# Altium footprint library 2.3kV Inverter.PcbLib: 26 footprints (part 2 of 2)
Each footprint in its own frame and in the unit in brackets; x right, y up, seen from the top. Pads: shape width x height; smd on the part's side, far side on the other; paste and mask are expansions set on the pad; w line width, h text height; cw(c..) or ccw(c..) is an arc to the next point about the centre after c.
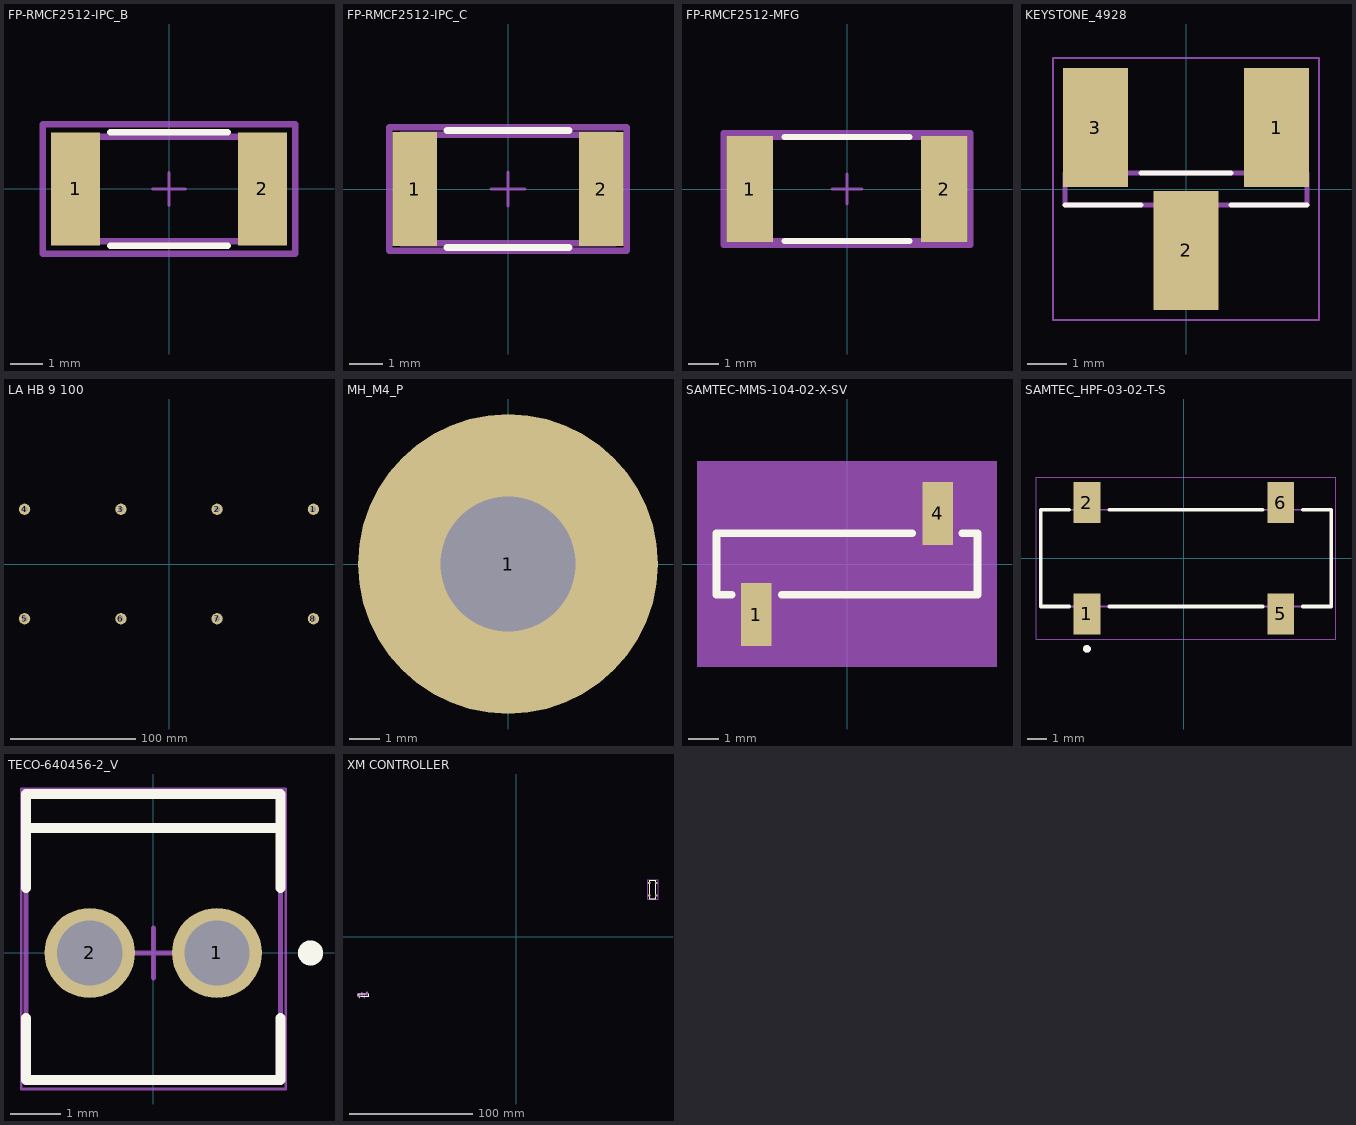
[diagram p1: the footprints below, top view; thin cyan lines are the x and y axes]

## FP-RMCF2512-IPC_B [mm]
pads (2):
  rect 1.504x3.455 smd paste+0 mask+0: 1(-2.851,0) 2(2.851,0)
Top Overlay:
  lines w0.2: -1.799,-1.727 1.799,-1.727 ; -1.799,1.727 1.799,1.727
Top Courtyard:
  lines w0.2: -3.853,-1.977 -3.853,1.977 3.853,1.977 3.853,-1.977 -3.853,-1.977
Top 3D Body:
  lines w0.2: -3.15,-1.6 -3.15,1.6 3.15,1.6 3.15,-1.6 -3.15,-1.6
Top Component Center:
  lines w0.1: -0.5,0 0.5,0 ; 0,-0.5 0,0.5
Top Assembly:
  lines w0.2: -3.853,-1.977 -3.853,1.977 3.853,1.977 3.853,-1.977 -3.853,-1.977
  text ".Designator" at 0,0.188 h1
3D body "Res_Stackpole_RMCF2512FT10M0_eec.STEP": height 0.25, standoff 0, extent -3.853,-1.977 3.853,1.977

## FP-RMCF2512-IPC_C [mm]
pads (2):
  rect 1.304x3.355 smd paste+0 mask+0: 1(-2.751,0) 2(2.751,0)
Top Overlay:
  lines w0.2: -1.799,-1.725 1.799,-1.725 ; -1.799,1.725 1.799,1.725
Top Courtyard:
  lines w0.2: -3.503,-1.825 -3.503,1.825 3.503,1.825 3.503,-1.825 -3.503,-1.825
Top 3D Body:
  lines w0.2: -3.15,-1.6 -3.15,1.6 3.15,1.6 3.15,-1.6 -3.15,-1.6
Top Component Center:
  lines w0.1: -0.5,0 0.5,0 ; 0,-0.5 0,0.5
Top Assembly:
  lines w0.2: -3.503,-1.825 -3.503,1.825 3.503,1.825 3.503,-1.825 -3.503,-1.825
  text ".Designator" at 0,0.188 h1
3D body "Res_Stackpole_RMCF2512FT10M0_eec.STEP": height 0.25, standoff 0, extent -3.503,-1.825 3.503,1.825

## FP-RMCF2512-MFG [mm]
pads (2):
  rect 1.55x3.5 smd paste+0 mask+0: 1(-3.225,0) 2(3.225,0)
Top Overlay:
  lines w0.2: -2.075,-1.725 2.075,-1.725 ; -2.075,1.725 2.075,1.725
Top Courtyard:
  lines w0.2: -4.1,-1.85 4.1,-1.85 4.1,1.85 -4.1,1.85 -4.1,-1.85
Top 3D Body:
  lines w0.2: -3.25,-1.725 3.25,-1.725 3.25,1.725 -3.25,1.725 -3.25,-1.725
Top Component Center:
  lines w0.1: -0.5,0 0.5,0 ; 0,-0.5 0,0.5
Top Assembly:
  lines w0.2: -4.1,-1.85 4.1,-1.85 4.1,1.85 -4.1,1.85 -4.1,-1.85
  text ".Designator" at 0,0.188 h1
3D body "Res_Stackpole_RMCF2512FT10M0_eec.STEP": height 0.25, standoff 0, extent -4.1,-1.85 4.1,1.85

## KEYSTONE_4928 [mm]
height 10.49
pads (3):
  rect 1.65x3 smd: 1(2.285,1.55) 2(0,-1.55) 3(-2.285,1.55)
Top Overlay:
  lines w0.127: -3.05,-0.405 -1.14,-0.405 ; -1.14,0.405 1.14,0.405 ; 1.14,-0.405 3.05,-0.405
Mechanical 13:
  lines w0.127: -3.05,-0.405 -3.05,0.405 3.05,0.405 3.05,-0.405 -3.05,-0.405
Mechanical 15:
  lines w0.05: -3.36,-3.3 3.36,-3.3 3.36,3.3 -3.36,3.3 -3.36,-3.3
3D body "4928.step": height 10.52, standoff 0.03, extent -3.048,-2.921 3.048,2.921

## LA HB 9 100 [mm]
pads (8):
  round 9 hole 4.5: 1(115.15,43.65) 2(38.38,43.65) 3(-38.38,43.65) 4(-115.15,43.65) 5(-115.15,-43.65) 6(-38.38,-43.65) 7(38.38,-43.65) 8(115.15,-43.65)
3D body "93070A095_Alloy Steel Low-Profile Socket Head Screw.STEP": height 2.75, standoff -6.05, extent -118.638,40.15 -111.662,47.15
3D body "93070A095_Alloy Steel Low-Profile Socket Head Screw.STEP": height 2.75, standoff -6.05, extent 111.662,40.15 118.638,47.15
3D body "93070A095_Alloy Steel Low-Profile Socket Head Screw.STEP": height 2.75, standoff -6.05, extent 111.662,-47.15 118.638,-40.15
3D body "93070A095_Alloy Steel Low-Profile Socket Head Screw.STEP": height 2.75, standoff -6.05, extent -118.638,-47.15 -111.662,-40.15
3D body "98269A123_Black-Oxide 18-8 Stainless Steel Washers.STEP": height -2.62, standoff -3.17, extent 111.15,39.65 119.15,47.65
3D body "98269A123_Black-Oxide 18-8 Stainless Steel Washers.STEP": height -2.62, standoff -3.17, extent 111.15,-47.65 119.15,-39.65
3D body "98269A123_Black-Oxide 18-8 Stainless Steel Washers.STEP": height -2.62, standoff -3.17, extent -119.15,-47.65 -111.15,-39.65
3D body "98269A123_Black-Oxide 18-8 Stainless Steel Washers.STEP": height -2.62, standoff -3.17, extent -119.15,39.65 -111.15,47.65
3D body "98269A123_Black-Oxide 18-8 Stainless Steel Washers.STEP": height -2.62, standoff -3.17, extent -42.38,39.65 -34.38,47.65
3D body "98269A123_Black-Oxide 18-8 Stainless Steel Washers.STEP": height -2.62, standoff -3.17, extent 34.38,39.65 42.38,47.65
3D body "98269A123_Black-Oxide 18-8 Stainless Steel Washers.STEP": height -2.62, standoff -3.17, extent 34.38,-47.65 42.38,-39.65
3D body "93070A095_Alloy Steel Low-Profile Socket Head Screw.STEP": height 2.75, standoff -6.05, extent 34.892,-47.15 41.868,-40.15
3D body "93070A095_Alloy Steel Low-Profile Socket Head Screw.STEP": height 2.75, standoff -6.05, extent 34.892,40.15 41.868,47.15
3D body "93070A095_Alloy Steel Low-Profile Socket Head Screw.STEP": height 2.75, standoff -6.05, extent -41.868,40.15 -34.892,47.15
3D body "93070A095_Alloy Steel Low-Profile Socket Head Screw.STEP": height 2.75, standoff -6.05, extent -41.868,-47.15 -34.892,-40.15
3D body "Heat Sink Assembly.STEP": height -0.41, standoff -98.41, extent -121.246,-88.528 121.754,49.477

## MH_M4_P [mm] "M4 plated mounting hole"
pads (1):
  round 10 hole 4.5: 1(0,0)
3D body "93369A127_Nylon Hex Nut.STEP": height 13.77, standoff 10.39, extent -3.45,-3.984 3.45,3.984
3D body "M4_50MM - Single.STEP": height 5.64, standoff -52.36, extent -4.619,-4 4.619,4
3D body "M4_50MM - Single.STEP": height -44.36, standoff -102.36, extent -4.619,-4 4.619,4
3D body "M4_07MM - Single.STEP": height 15, standoff 0, extent -4.619,-4 4.619,4
3D body "98269A123_Black-Oxide 18-8 Stainless Steel Washers.STEP": height 10.48, standoff 9.92, extent -4,-4 4,4

## SAMTEC-MMS-104-02-X-SV [mm]
pads (2):
  rect 1.016x2.085 smd mask+0: 1(-3,-1.677) 4(3,1.677)
Top Overlay:
  lines w0.254: -3.81,-1.016 -4.318,-1.016 -4.318,1.016 2.159,1.016 ; -2.159,-1.016 4.318,-1.016 4.318,1.016 3.81,1.016
Top Paste:
  region: 3.508,0.634 2.492,0.634 2.492,2.719 3.508,2.719
  region: 1.508,-2.72 0.492,-2.72 0.492,-0.635 1.508,-0.635
  region: -0.492,0.634 -1.508,0.634 -1.508,2.719 -0.492,2.719
  region: -2.492,-2.72 -3.508,-2.72 -3.508,-0.635 -2.492,-0.635
Top Solder:
  region: 3.559,0.584 2.441,0.584 2.441,2.77 3.559,2.77
  region: 1.559,-2.77 0.441,-2.77 0.441,-0.584 1.559,-0.584
  region: -0.441,0.584 -1.559,0.584 -1.559,2.77 -0.441,2.77
  region: -2.441,-2.77 -3.559,-2.77 -3.559,-0.584 -2.441,-0.584
Mechanical 13:
  lines w0.1: -3.254,-0.999 -3.254,-2.219 -2.746,-2.219 -2.746,-0.999 ; -3.254,-0.356 -3.254,-0.305 -2.746,-0.305 -2.746,-0.356 ; -2.001,-0.999 -4.279,-0.999 -4.279,0.999 -2.001,0.999 ; -1.999,-0.999 -0.001,-0.999 ; -1.999,0.999 -0.001,0.999 ; -1.254,0.356 -1.254,0.305 -0.746,0.305 -0.746,0.356 ; -1.254,0.999 -1.254,2.219 -0.746,2.219 -0.746,0.999 ; 0.001,-0.999 1.999,-0.999 ; 0.001,0.999 1.999,0.999 ; 0.746,-0.999 0.746,-2.219 1.254,-2.219 1.254,-0.999 ; 0.746,-0.356 0.746,-0.305 1.254,-0.305 1.254,-0.356 ; 2.001,-0.999 4.279,-0.999 4.279,0.999 2.001,0.999 ; 2.746,0.356 2.746,0.305 3.254,0.305 3.254,0.356 ; 2.746,0.999 2.746,2.219 3.254,2.219 3.254,0.999 ; -3.356,-0.356 -2.644,-0.356 -2.644,0.356 -3.356,0.356 -3.356,-0.356 ; -1.356,-0.356 -0.644,-0.356 -0.644,0.356 -1.356,0.356 -1.356,-0.356 ; 0.644,-0.356 1.356,-0.356 1.356,0.356 0.644,0.356 0.644,-0.356 ; 2.644,-0.356 3.356,-0.356 3.356,0.356 2.644,0.356 2.644,-0.356
Mechanical 15:
  region: 4.964,-3.406 -4.964,-3.406 -4.964,3.406 4.964,3.406
3D body "MMS-104-02-L-SV-K-TR.stp": height 4.65, standoff 0.03, extent -4.277,-2.219 4.277,2.219

## SAMTEC_HPF-03-02-T-S [mm]
pads (4):
  rect 1.4x2.16 smd: 1(-5.08,-2.92) 2(-5.08,2.92) 5(5.08,-2.92) 6(5.08,2.92)
Top Overlay:
  circle w0.2: c-5.08,-4.76 r0.1
  lines w0.2: -6.016,-2.54 -7.506,-2.54 -7.506,2.54 -6.016,2.54 ; -3.916,-2.54 4.144,-2.54 ; -3.916,2.54 4.144,2.54 ; 6.244,-2.54 7.734,-2.54 7.734,2.54 6.244,2.54
Mechanical 13:
  circle w0.2: c-5.08,-4.76 r0.1
  lines w0.1: -7.506,-2.54 -7.506,2.54 7.734,2.54 7.734,-2.54 -7.506,-2.54
Mechanical 15:
  lines w0.05: -7.756,-4.25 -7.756,4.25 7.984,4.25 7.984,-4.25 -7.756,-4.25
3D body "HPF-03-02-T-S.step": height 9.35, standoff 0, extent -7.62,-3.556 7.62,3.556

## TECO-640456-2_V [mm] "HDR, 2-Leads, Body 5.715x5.08mm, Pitch 2.54mm"
height 10.49
pads (2):
  round 1.8 hole 1.3: 1(1.27,0) 2(-1.27,0)
Top Overlay:
  circle w0.25: c3.14,0 r0.125
  lines w0.2: -2.54,-1.3 -2.54,-2.54 2.54,-2.54 2.54,-1.3 ; -2.54,1.3 -2.54,3.175 2.54,3.175 2.54,1.3 ; -2.54,2.5 2.54,2.5
Mechanical 13:
  lines w0.1: -2.54,-2.54 -2.54,3.175 2.54,3.175 2.54,-2.54 -2.54,-2.54
Mechanical 15:
  lines w0.05: -2.64,-2.717 2.64,-2.717 2.64,3.275 -2.64,3.275 -2.64,-2.717
  lines w0.1: -0.5,0 0.5,0 ; 0,-0.5 0,0.5
3D body "TE 640456-2 Color.STEP": height 10.09, standoff -3.5, extent -2.54,-2.667 2.54,3.175

## XM CONTROLLER [mm]
pads (6):
  rect 2.16x1.4 smd: 1(108.205,43.688) 2(114.045,43.688) 5(108.205,33.528) 6(114.045,33.528)
  rect 1.016x2.085 smd: 11(-127.282,-48.921) 14(-121.282,-45.567)
Top Overlay:
  lines w0.2: 108.585,32.364 108.585,30.874 113.665,30.874 113.665,32.364 ; 108.585,34.671 108.585,42.524 ; 108.585,44.831 108.585,46.114 113.665,46.114 113.665,44.831 ; 113.665,34.671 113.665,42.524
  lines w0.254: -128.219,-48.26 -128.6,-48.26 -128.6,-46.228 -122.123,-46.228 ; -126.441,-48.26 -119.964,-48.26 -119.964,-46.228 -120.345,-46.228
Mechanical 13:
  lines w0.1: -127.536,-48.243 -127.536,-49.463 -127.028,-49.463 -127.028,-48.243 ; -127.536,-47.6 -127.536,-47.549 -127.028,-47.549 -127.028,-47.6 ; -126.283,-48.243 -128.561,-48.243 -128.561,-46.245 -126.283,-46.245 ; -126.281,-48.243 -124.283,-48.243 ; -126.281,-46.245 -124.283,-46.245 ; -125.536,-46.888 -125.536,-46.939 -125.028,-46.939 -125.028,-46.888 ; -125.536,-46.245 -125.536,-45.025 -125.028,-45.025 -125.028,-46.245 ; -124.281,-48.243 -122.283,-48.243 ; -124.281,-46.245 -122.283,-46.245 ; -123.536,-48.243 -123.536,-49.463 -123.028,-49.463 -123.028,-48.243 ; -123.536,-47.6 -123.536,-47.549 -123.028,-47.549 -123.028,-47.6 ; -122.281,-48.243 -120.003,-48.243 -120.003,-46.245 -122.281,-46.245 ; -121.536,-46.888 -121.536,-46.939 -121.028,-46.939 -121.028,-46.888 ; -121.536,-46.245 -121.536,-45.025 -121.028,-45.025 -121.028,-46.245 ; -127.638,-47.6 -127.638,-46.888 -126.926,-46.888 -126.926,-47.6 -127.638,-47.6 ; -125.638,-47.6 -125.638,-46.888 -124.926,-46.888 -124.926,-47.6 -125.638,-47.6 ; -123.638,-47.6 -123.638,-46.888 -122.926,-46.888 -122.926,-47.6 -123.638,-47.6 ; -121.638,-47.6 -121.638,-46.888 -120.926,-46.888 -120.926,-47.6 -121.638,-47.6 ; 108.585,30.874 113.665,30.874 113.665,46.114 108.585,46.114 108.585,30.874
Mechanical 15:
  lines w0.05: 106.875,30.624 115.375,30.624 115.375,46.364 106.875,46.364 106.875,30.624
3D body "MTMM-104-14-G-S-560.stp": height 19.89, standoff 0.82, extent -128.282,-48.243 -120.282,-46.245
3D body "92492A216_Nylon Pan Head Phillips Screws.STEP": height 12.95, standoff 3.85, extent 125,-53.197 133,-45.197
3D body "92492A216_Nylon Pan Head Phillips Screws.STEP": height 12.95, standoff 3.85, extent 23.999,-35.203 31.999,-27.203
3D body "92492A216_Nylon Pan Head Phillips Screws.STEP": height 12.95, standoff 3.85, extent -32.001,-35.203 -24.001,-27.203
3D body "92492A216_Nylon Pan Head Phillips Screws.STEP": height 12.95, standoff 3.85, extent -119.091,-41.423 -111.091,-33.423
3D body "92492A216_Nylon Pan Head Phillips Screws.STEP": height 12.95, standoff 3.85, extent 125,27.2 133,35.2
3D body "92492A216_Nylon Pan Head Phillips Screws.STEP": height 12.95, standoff 3.85, extent -4,40.504 4,48.504
3D body "92492A216_Nylon Pan Head Phillips Screws.STEP": height 12.95, standoff 3.85, extent -119.116,40.504 -111.116,48.504
3D body "93369A127_Nylon Hex Nut.STEP": height 21.69, standoff 18.31, extent 125.55,-53.181 132.45,-45.213
3D body "93369A127_Nylon Hex Nut.STEP": height 21.69, standoff 18.31, extent 24.549,-35.187 31.449,-27.219
3D body "93369A127_Nylon Hex Nut.STEP": height 21.69, standoff 18.31, extent -31.451,-35.187 -24.551,-27.219
3D body "93369A127_Nylon Hex Nut.STEP": height 21.69, standoff 18.31, extent -118.541,-41.407 -111.641,-33.439
3D body "93369A127_Nylon Hex Nut.STEP": height 21.69, standoff 18.31, extent 125.55,27.216 132.45,35.184
3D body "93369A127_Nylon Hex Nut.STEP": height 21.69, standoff 18.31, extent -3.45,40.52 3.45,48.488
3D body "93369A127_Nylon Hex Nut.STEP": height 21.69, standoff 18.31, extent -118.541,40.52 -111.641,48.488
3D body "HPF-03-02-T-S.step": height 9.35, standoff 0, extent 107.569,30.988 114.681,46.228
3D body "MMS-104-02-L-SV-K-TR.stp": height 4.57, standoff -0.05, extent -128.56,-49.463 -120.005,-45.025
3D body "M4_07MM - Single.STEP": height 24.54, standoff 9.54, extent -119.71,40.504 -110.472,48.504
3D body "M4_07MM - Single.STEP": height 24.54, standoff 9.54, extent -4.619,40.504 4.619,48.504
3D body "M4_07MM - Single.STEP": height 24.54, standoff 9.54, extent 124.381,27.2 133.619,35.2
3D body "M4_07MM - Single.STEP": height 24.54, standoff 9.54, extent -32.62,-35.203 -23.382,-27.203
3D body "M4_07MM - Single.STEP": height 24.54, standoff 9.54, extent 23.38,-35.203 32.618,-27.203
3D body "M4_07MM - Single.STEP": height 24.54, standoff 9.54, extent 124.381,-53.197 133.619,-45.197
3D body "M4_07MM - Single.STEP": height 24.54, standoff 9.54, extent -119.71,-41.423 -110.472,-33.423
3D body "XM Controller.STEP": height -2.16, standoff -37.99, extent -141.039,-55.197 135,50.8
